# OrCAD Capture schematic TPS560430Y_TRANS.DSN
size C; title: TPS560430Y SIMPLE SWITCHER® 4-V to 36-V, 600-mA; note: Datasheet: SLVSE22B     EVM: SLVUB52; note: Synchronous Step-Down Converter
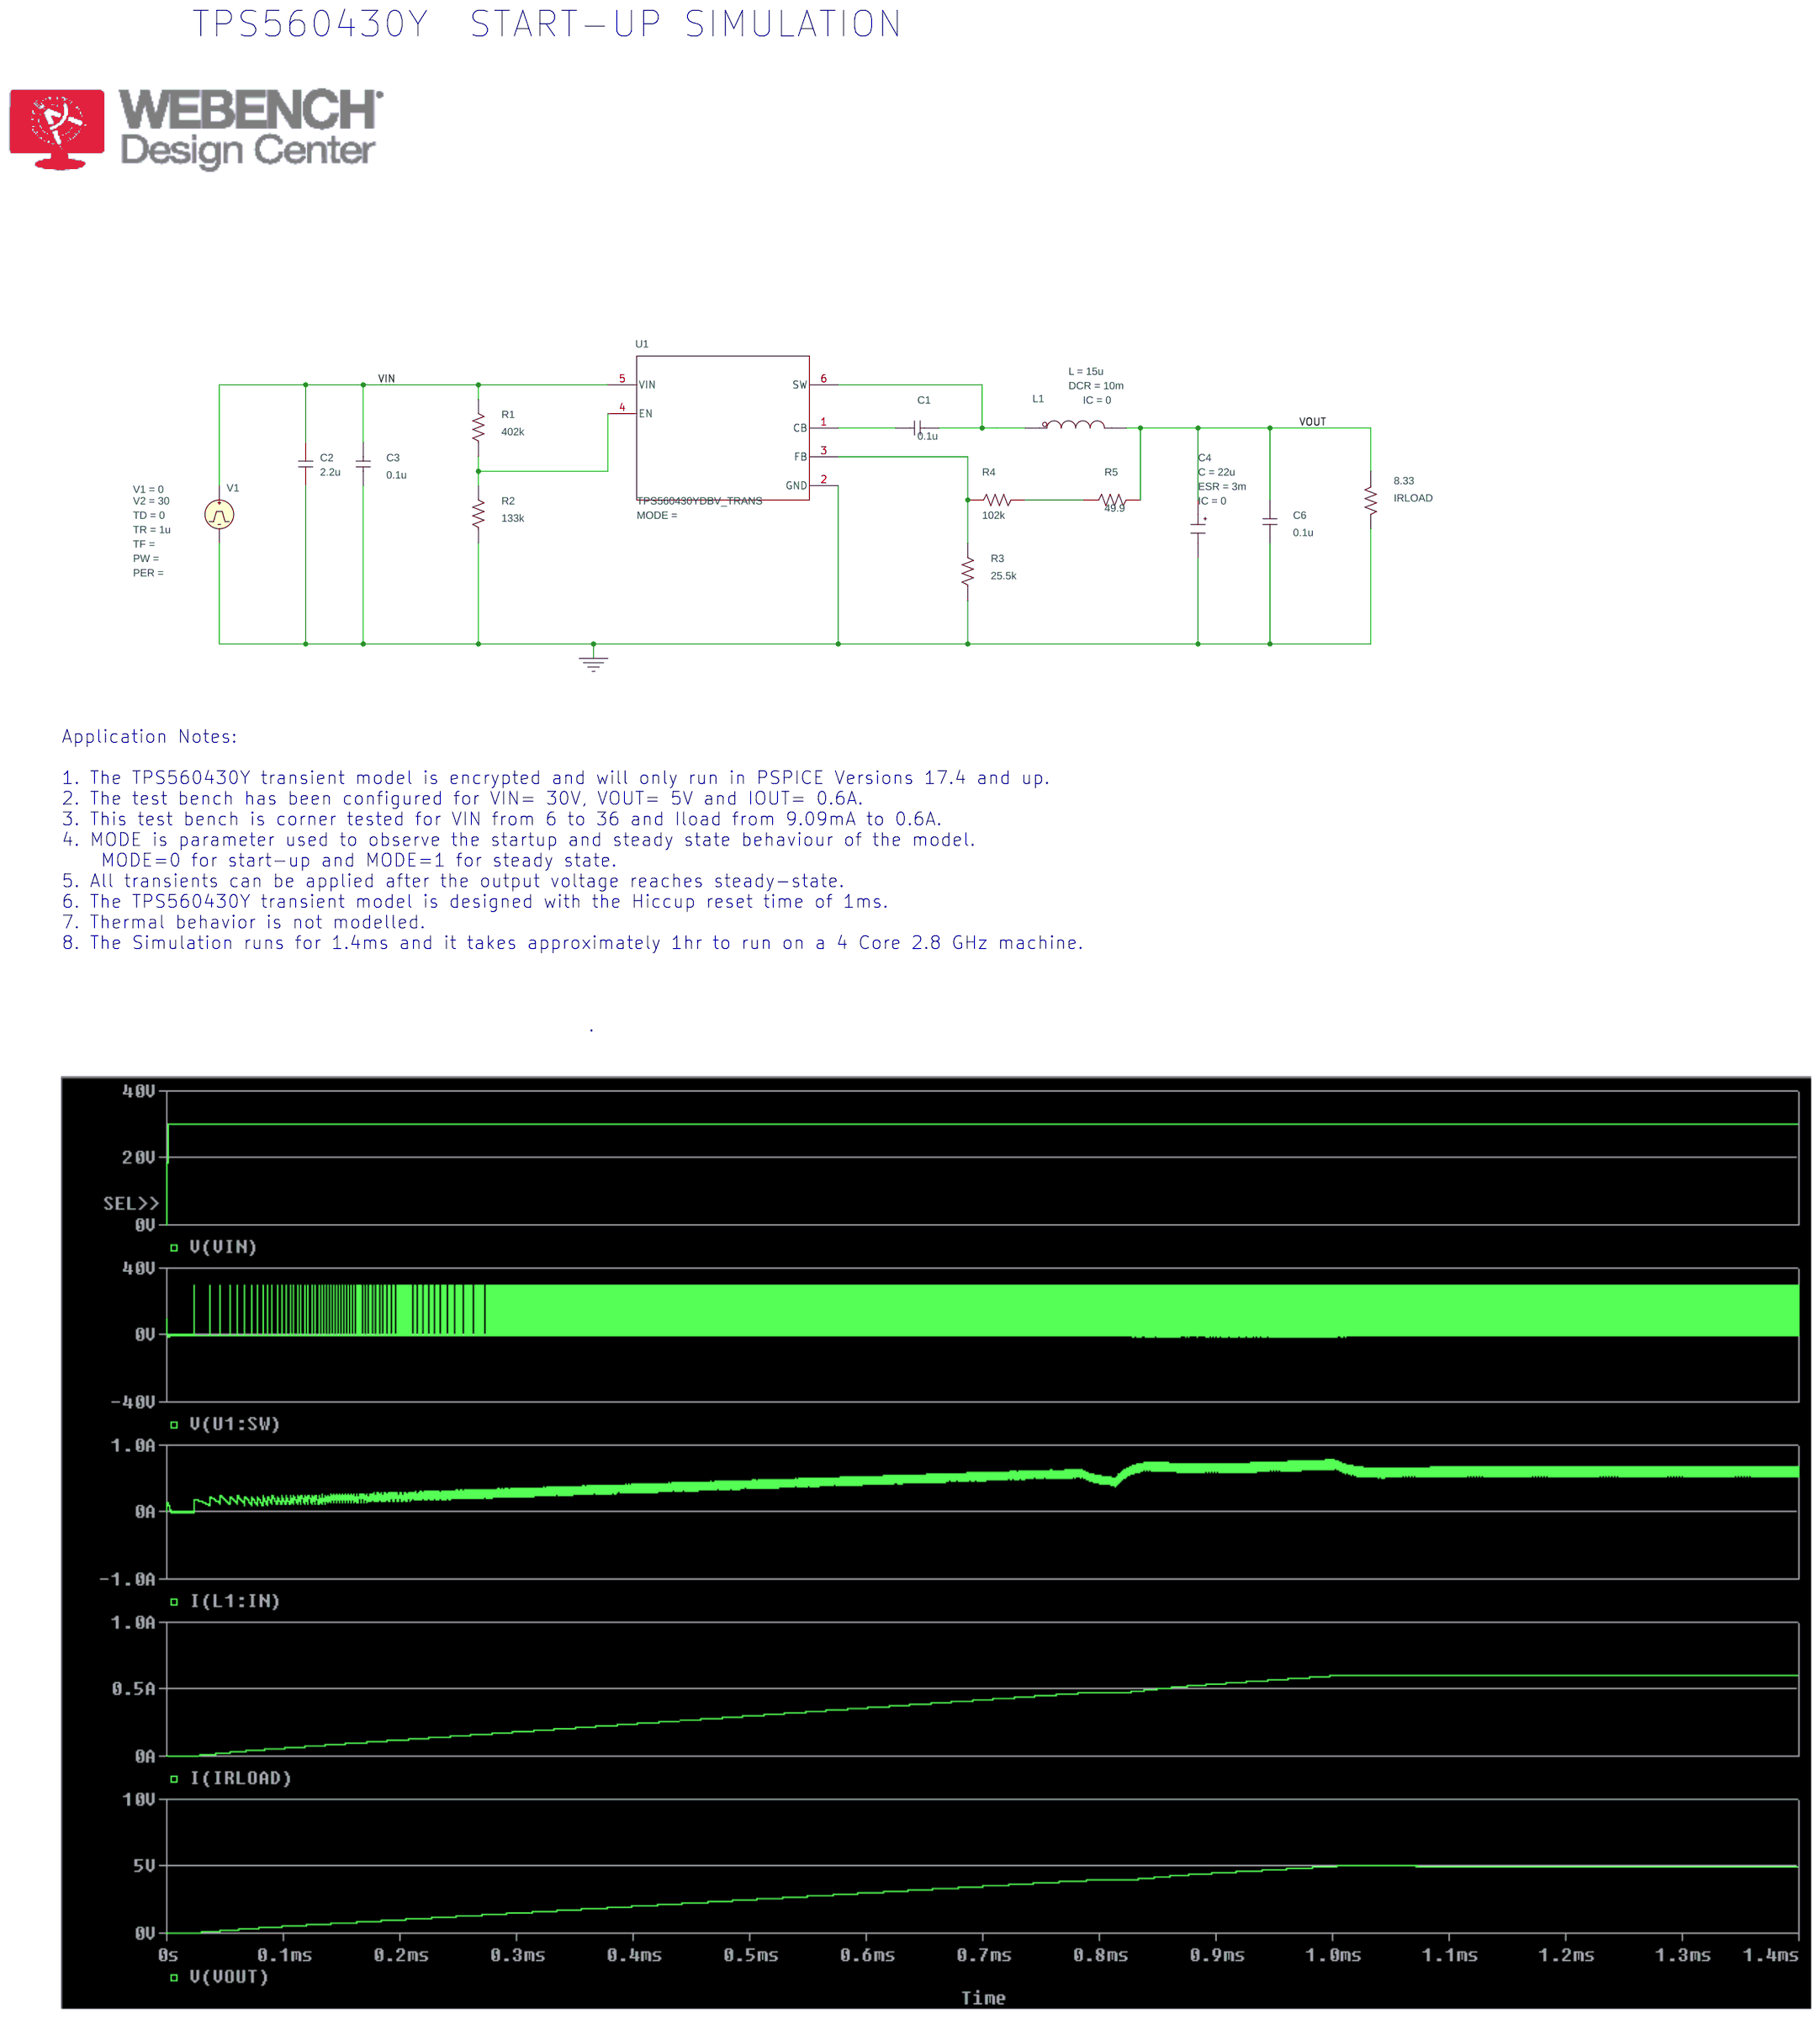
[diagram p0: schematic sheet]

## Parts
C1  0.1u  [RAD/CK05]
C2  2.2u  [RAD/CK05]
C3  0.1u  [RAD/CK05]
C4  CESR
C6  0.1u  [RAD/CK05]
IRLOAD  8.33  [AX/RC05]
L1  LDCR
R1  402k  [AX/RC05]
R2  133k  [AX/RC05]
R3  25.5k  [RC05]
R4  102k  [RC05]
R5  49.9  [AX/RC05]
U1  TPS560430YDBV_TRANS  [DBV0006A_N]
V1  VPULSE

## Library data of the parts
C1 = C: IC: -3.3
C2 C3 C6 = C
C4 = CESR_0: C: 22u; ESR: 3m; IC: 0; PSpiceTemplate: X^@REFDES %IN %OUT @MODEL PARAMS:  ?C|C=@C||C=100u|  ?ESR|ESR=@ESR||ESR=0.01| ?X|X=@X||X=2|  ?IC|IC=@IC||IC=2|; X: 1
IRLOAD R1-R5 = R
L1 = LDCR_0: DCR: 10m; IC: 0; L: 15u; PSpiceTemplate: X^@REFDES %IN %OUT @MODEL PARAMS:  ?L|L=@L||L=1u|  ?DCR|DCR=@DCR||DCR=0.01| ?IC|IC=@IC||IC=0|
U1 = TPS560430YDBV_TRANS
V1 = VPULSE: TD: 0; TR: 1u; V1: 0; V2: 30

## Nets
VIN: C2.2 C3.2 R1.2 U1.5(VIN) V1.1(+)
0: C2.1 C3.1 C4.3(OUT) C6.1 IRLOAD.2 R2.1 R3.1 U1.2(GND) V1.2(-)
VOUT: C4.1(IN) C6.2 IRLOAD.1 L1.3(OUT) R5.2
N16766833: R1.1 R2.2 U1.4(EN)
N16767366: C1.1 U1.1(CB)
N16767372: C1.2 L1.1(IN) U1.6(SW)
N16767532: R4.2 R5.1
N16767538: R3.2 R4.1 U1.3(FB)

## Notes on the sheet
- TPS560430Y  START-UP SIMULATION
- Application Notes:
  1. The TPS560430Y transient model is encrypted and will only run in PSPICE Versions 17.4 and up.
  2. The test bench has been configured for VIN= 30V, VOUT= 5V and IOUT= 0.6A.
  3. This test bench is corner tested for VIN from 6 to 36 and Iload from 9.09mA to 0.6A.
  4. MODE is parameter used to observe the startup and steady state behaviour of the model.
      MODE=0 for start-up and MODE=1 for steady state.
  5. All transients can be applied after the output voltage reaches steady-state.
  6. The TPS560430Y transient model is designed with the Hiccup reset time of 1ms.
  7. Thermal behavior is not modelled.
  8. The Simulation runs for 1.4ms and it takes approximately 1hr to run on a 4 Core 2.8 GHz machine.
                                                        .
